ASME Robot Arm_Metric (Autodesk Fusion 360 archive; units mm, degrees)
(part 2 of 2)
sketch "Sketch6" plane through (0, 0, 5) normal (0, 0, 1) x axis (1, 0, 0)
  line L1 (2, 0) -> (-2, 0)
  line L2 (-2, 1.1547) -> (0, 0)
  line L3 (-2, 1.1547) -> (-2, -1.1547)
  line L4 (0, 0) -> (-2, -1.1547)
  point P1 (0, 0)
  point P4 (0, 0)
  point P2 (-2, 0)
  point P5 (-2, 1.1547)
  point P7 (-2, 1.1547)
  point P8 (0, 0)
  point P3 (2, 0)
  horizontal L1
  midpoint P1 L1
  coincident P1 P4
  perpendicular L1 L3
  midpoint P2 L3
  coincident P5 P7
  coincident P1 P8
  dimension "d72" distance P2 P3 = 4 (= "adsk_philwidth")
  dimension "d100" angle L1 L2 = 150
extrude "Extrude1" cut sketch "Sketch6" profile of L2 L3 L4 no distance stored
circular_pattern "C-Pattern1" TotalAngle 360
extrude "Extrude2" cut of existing geometry no distance stored taper -85
thread "Thread2" ThreadOffset 0 ThreadLength 5.9092 (= "adsk_thrlen")
fillet "Fillet4" radius 0.5 (= "adsk_nomdia * 0.1")
sketch "Sketch7" plane through (0, 0, 0) normal (0, 1, 0) x axis (1, 0, 0)
  line L1 (-2.55, 7.5092) -> (-2.55, 8)
  line L2 (-2.0092, 8) -> (-2.55, 7.5092)
  line L3 (0, -5) -> (0, 8)
  line L4 (0, 8) -> (-2.55, 8)
  point P5 (0, 8)
  point P7 (0, 8)
  point P4 (-2.0092, 8)
  point P3 (-2.55, 7.5092)
  point P1 (0, 0)
  coincident P5 P7
  perpendicular L3 L4
  coincident P4 L4
  perpendicular L1 L4
  dimension "d92" distance P3 P4 = 0.4908 (= "adsk_startlen")
  dimension "d98" distance P1 P4 = 2.0092 (= "adsk_endpointdia / 2")
  dimension "d99" distance P1 L1 = 2.55 (= "adsk_nomdia * 0.51")
revolve "Revolve3" sketch "Sketch7" AlongAngle 360
joint_origin "JointOrigin2" OffsetX 0 OffsetY 0 OffsetZ 0 AngleZ 0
